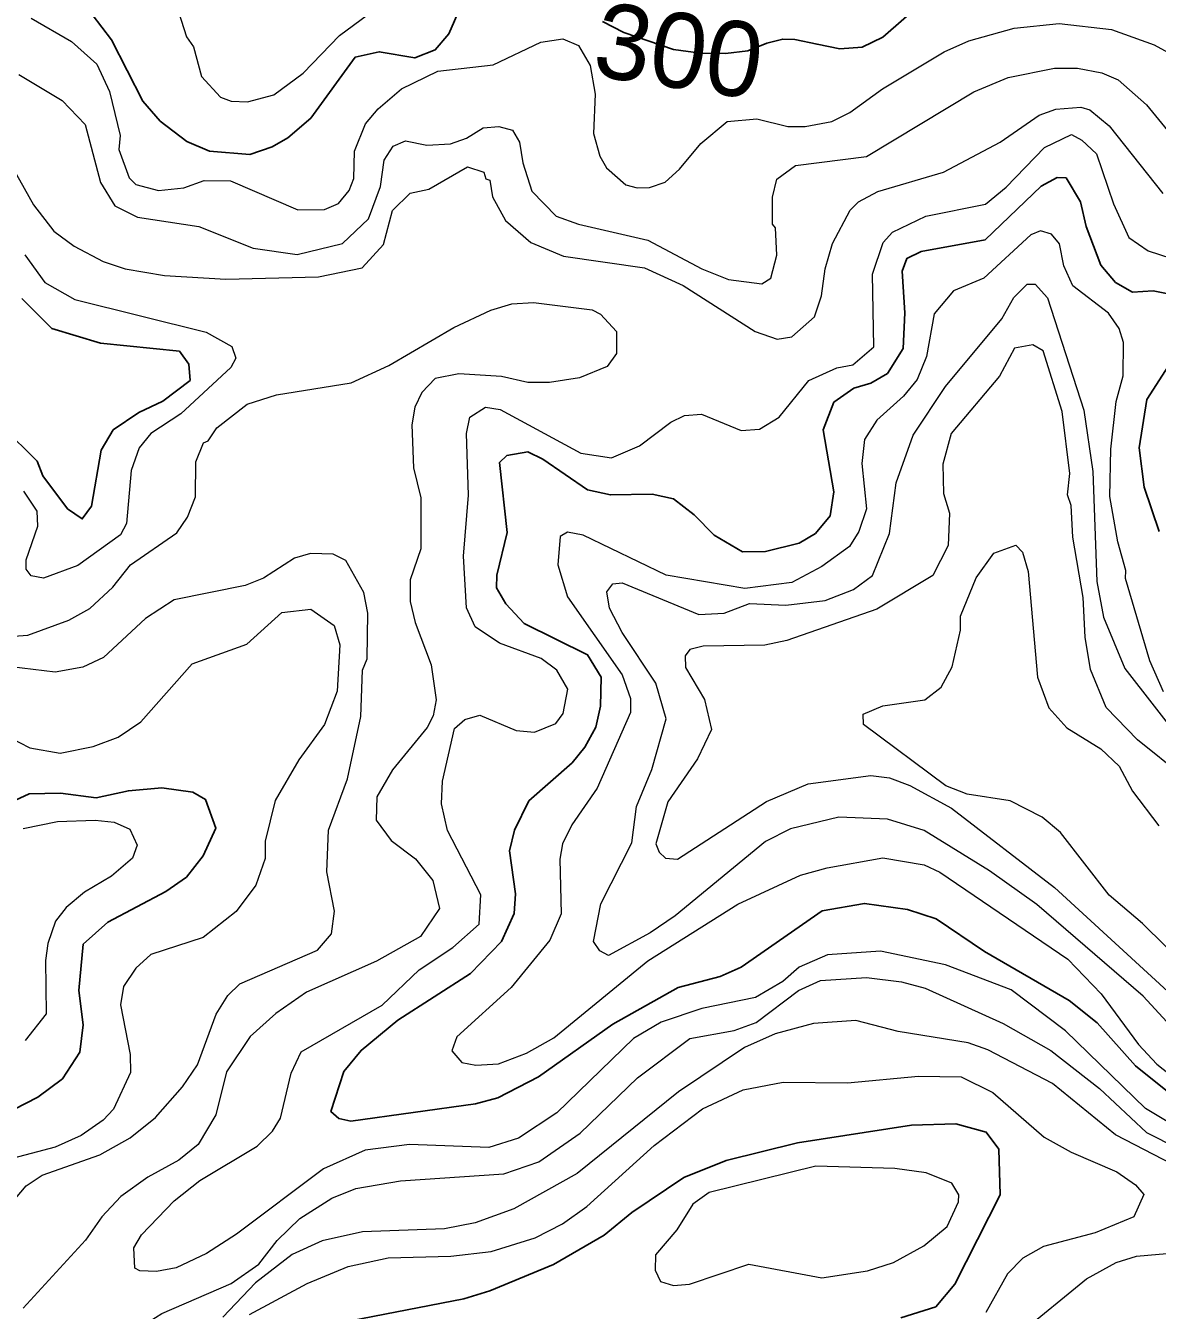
# Model space of a CAD drawing. Extents: x 673.6 to 698.9, y 7012 to 7040.1.
# Drawn here: x 687.168 to 688.374, y 7015.259 to 7016.629 of the extents above; entities that cross this region are included whole.
import ezdxf
from ezdxf.enums import TextEntityAlignment as Align

# ---------------------------------------------------------------- set-up
doc = ezdxf.new("R2010")
doc.units = 0
doc.header["$LTSCALE"] = 0.032
doc.layers.add('1', color=7, linetype='Continuous', lineweight=25)
doc.layers.add('2', color=7, linetype='Continuous', lineweight=13)
doc.layers.add('61', color=7, linetype='Continuous')

msp = doc.modelspace()

# ---------------------------------------------------------------- linework, layer by layer
at = {"layer": '1'}
for points in [[(687.2385, 7016.6409), (687.2594, 7016.6137), (687.2927, 7016.5483), (687.3111, 7016.5273), (687.3397, 7016.5055), (687.3639, 7016.495), (687.4067, 7016.4917), (687.4305, 7016.4996), (687.4472, 7016.5092), (687.4716, 7016.5304), (687.5189, 7016.5953), (687.5448, 7016.6011), (687.5825, 7016.5945), (687.6045, 7016.6033), (687.6189, 7016.6202), (687.6311, 7016.6479)], [(687.7826, 7016.6335), (687.8056, 7016.6218), (687.8586, 7016.6034), (687.8873, 7016.5996), (687.9139, 7016.5993), (687.9376, 7016.6022), (687.9581, 7016.6102), (687.9749, 7016.6147), (687.988, 7016.6141), (688.0115, 7016.6092), (688.0357, 7016.6043), (688.0595, 7016.6061), (688.0816, 7016.6168), (688.1237, 7016.6532)], [(688.1052, 7016.3226), (688.1024, 7016.3672), (688.1073, 7016.3808), (688.1224, 7016.3882), (688.1909, 7016.4007), (688.2504, 7016.4577)], [(688.2504, 7016.4577), (688.2674, 7016.467), (688.2771, 7016.4667), (688.2923, 7016.4411), (688.2983, 7016.4148), (688.314, 7016.3734), (688.3299, 7016.3549), (688.348, 7016.3446), (688.3699, 7016.3461), (688.4022, 7016.3397)], [(687.1637, 7016.3381), (687.1956, 7016.306), (687.2476, 7016.2903), (687.3317, 7016.282), (687.3416, 7016.2681), (687.343, 7016.2507), (687.3139, 7016.2284), (687.2883, 7016.2163), (687.261, 7016.1979), (687.2482, 7016.1761), (687.2379, 7016.1164), (687.2281, 7016.1029), (687.2124, 7016.1136), (687.1859, 7016.1489), (687.1799, 7016.1644), (687.1433, 7016.2008)], [(688.3851, 7015.4922), (688.351, 7015.5196), (688.3102, 7015.5656), (688.2802, 7015.5895), (688.1902, 7015.6417), (688.1384, 7015.6763), (688.108, 7015.6864), (688.062, 7015.6929), (688.0168, 7015.6848), (687.9305, 7015.625), (687.9083, 7015.615), (687.8636, 7015.6033), (687.7937, 7015.5642), (687.7145, 7015.5078), (687.671, 7015.4857), (687.6474, 7015.4791), (687.5145, 7015.4605), (687.5015, 7015.4636), (687.4932, 7015.4709), (687.507, 7015.5138), (687.5253, 7015.5362), (687.5644, 7015.5685), (687.6419, 7015.618), (687.6752, 7015.6524), (687.6886, 7015.6823), (687.69, 7015.7031), (687.6837, 7015.7488), (687.6889, 7015.7711), (687.7042, 7015.8022), (687.7504, 7015.8429), (687.7639, 7015.8594), (687.7757, 7015.8807), (687.7805, 7015.9033), (687.7814, 7015.9342), (687.7668, 7015.958), (687.6993, 7015.9913), (687.6798, 7016.0123), (687.6699, 7016.0295), (687.67, 7016.043), (687.6812, 7016.0883), (687.6731, 7016.163), (687.6807, 7016.1704), (687.703, 7016.1744), (687.7193, 7016.1668), (687.7667, 7016.134), (687.7912, 7016.1285), (687.8356, 7016.1292), (687.8586, 7016.1242), (687.8805, 7016.1073), (687.9017, 7016.0855), (687.9322, 7016.0678), (687.9567, 7016.0682), (687.9926, 7016.0772), (688.0098, 7016.0874), (688.0256, 7016.1064), (688.0294, 7016.1319), (688.0182, 7016.1979), (688.0293, 7016.2273), (688.0506, 7016.2425), (688.069, 7016.2477), (688.0868, 7016.2582), (688.1032, 7016.2848), (688.1052, 7016.3226)], [(688.4088, 7016.3011), (688.3633, 7016.2303), (688.355, 7016.1788), (688.3604, 7016.1367), (688.3762, 7016.0894)], [(687.1057, 7015.7797), (687.1716, 7015.8096), (687.2047, 7015.8105), (687.2429, 7015.8056), (687.2772, 7015.813), (687.3128, 7015.8162), (687.346, 7015.8116), (687.3595, 7015.8038), (687.3704, 7015.7731), (687.3571, 7015.7436), (687.3391, 7015.7209), (687.3171, 7015.7056), (687.2552, 7015.673), (687.2292, 7015.6496), (687.2243, 7015.6001), (687.2291, 7015.5635), (687.2253, 7015.5341), (687.207, 7015.5059), (687.1806, 7015.4863), (687.1042, 7015.4472)], [(687.5139, 7015.2476), (687.6348, 7015.2713), (687.6627, 7015.2798), (687.7304, 7015.3079), (687.7846, 7015.339), (687.8141, 7015.3631), (687.8693, 7015.4007), (687.9145, 7015.4188), (687.9905, 7015.4374), (688.1121, 7015.4563), (688.1594, 7015.4579), (688.1919, 7015.449), (688.2053, 7015.4308), (688.2068, 7015.382), (688.1583, 7015.2868), (688.138, 7015.2628), (688.101, 7015.2508)]]:
    msp.add_lwpolyline(points, dxfattribs=at)
at = {"layer": '2'}
for points in [[(687.0418, 7016.6363), (687.0645, 7016.5815), (687.0906, 7016.5473), (687.1226, 7016.5234), (687.1479, 7016.488), (687.1762, 7016.4378)], [(687.1737, 7016.6368), (687.2166, 7016.6121), (687.2435, 7016.588), (687.2572, 7016.5587), (687.2685, 7016.5118), (687.2672, 7016.4969), (687.2781, 7016.4668), (687.2852, 7016.4597), (687.3094, 7016.4531), (687.3365, 7016.4561), (687.3581, 7016.4638), (687.386, 7016.4636), (687.4579, 7016.4325), (687.4863, 7016.4328), (687.5013, 7016.4393), (687.5128, 7016.4532), (687.5177, 7016.4661), (687.5185, 7016.495), (687.53, 7016.5243), (687.5434, 7016.5404), (687.5686, 7016.5617), (687.6072, 7016.5804), (687.6661, 7016.5873), (687.717, 7016.6115), (687.7406, 7016.615), (687.7572, 7016.6078), (687.7695, 7016.5864), (687.7748, 7016.5558), (687.7733, 7016.5141), (687.7799, 7016.4897), (687.7869, 7016.4773), (687.8076, 7016.4593)], [(687.3307, 7016.6439), (687.3391, 7016.6172), (687.3467, 7016.6064), (687.3553, 7016.5749), (687.3753, 7016.5528), (687.3869, 7016.5484), (687.4042, 7016.5476), (687.4323, 7016.5552), (687.4636, 7016.5782), (687.5022, 7016.6185), (687.5322, 7016.6407)], [(687.8877, 7016.5034), (687.9157, 7016.5269), (687.9473, 7016.5295), (687.9803, 7016.5213), (687.999, 7016.5213), (688.0272, 7016.5268), (688.0463, 7016.5362), (688.0814, 7016.5615), (688.1471, 7016.6009), (688.1732, 7016.6127), (688.2218, 7016.6264), (688.2695, 7016.6313), (688.3254, 7016.6248), (688.3711, 7016.6085), (688.4555, 7016.5622), (688.4839, 7016.5575), (688.5124, 7016.5655), (688.5637, 7016.5952), (688.5831, 7016.6033), (688.6472, 7016.6182), (688.7021, 7016.6375)], [(688.2892, 7016.5837), (688.315, 7016.5787), (688.3326, 7016.5713), (688.3629, 7016.5445), (688.3917, 7016.5092), (688.4241, 7016.4864), (688.4442, 7016.4798), (688.4802, 7016.4792), (688.4969, 7016.4827), (688.5131, 7016.4926), (688.5245, 7016.4952), (688.6344, 7016.559), (688.7191, 7016.5916), (688.7324, 7016.5909), (688.758, 7016.5998), (689.0062, 7016.6282), (689.0534, 7016.6389)], [(687.9884, 7016.4799), (688.0644, 7016.4894), (688.1787, 7016.5584), (688.2153, 7016.5738), (688.2646, 7016.5837), (688.2892, 7016.5837)], [(687.1606, 7016.5768), (687.2065, 7016.549), (687.2311, 7016.5234), (687.2474, 7016.4618), (687.2628, 7016.4369), (687.2869, 7016.4247), (687.3523, 7016.4147), (687.4102, 7016.3918), (687.4573, 7016.3849), (687.5056, 7016.3966), (687.5334, 7016.423), (687.5461, 7016.4576), (687.5498, 7016.4854), (687.5596, 7016.5006), (687.5726, 7016.5063), (687.5954, 7016.5016), (687.6207, 7016.503), (687.6378, 7016.5089), (687.6554, 7016.5199), (687.6722, 7016.5213), (687.6867, 7016.5177), (687.6943, 7016.5047), (687.6977, 7016.4827), (687.7073, 7016.4526), (687.7333, 7016.4258), (687.7571, 7016.4173), (687.831, 7016.4003), (687.8888, 7016.3697), (687.917, 7016.3583), (687.9528, 7016.3537), (687.9623, 7016.3597), (687.9686, 7016.3844), (687.9671, 7016.4133), (687.9639, 7016.4172), (687.9639, 7016.446), (687.9687, 7016.4651), (687.9884, 7016.4799)], [(687.1762, 7016.4378), (687.1977, 7016.4098), (687.2196, 7016.3937), (687.2505, 7016.3774), (687.2738, 7016.3696), (687.3158, 7016.3625), (687.3813, 7016.3586), (687.4798, 7016.3611), (687.5264, 7016.3708), (687.5493, 7016.3955), (687.559, 7016.4318), (687.5778, 7016.4505), (687.5975, 7016.4547), (687.6387, 7016.4783), (687.6562, 7016.4728), (687.6583, 7016.4657), (687.6628, 7016.4643), (687.6656, 7016.4466), (687.6795, 7016.4211), (687.7064, 7016.3978), (687.741, 7016.3831), (687.8277, 7016.3707), (687.8689, 7016.3519), (687.9454, 7016.3028), (687.9691, 7016.2945), (687.9847, 7016.297), (688.0088, 7016.3183), (688.0164, 7016.3408), (688.02, 7016.3696), (688.0281, 7016.3968), (688.0467, 7016.4322), (688.0556, 7016.4412), (688.0762, 7016.4522), (688.1464, 7016.4727), (688.2068, 7016.5047), (688.2482, 7016.5335), (688.2662, 7016.5401), (688.2926, 7016.5419), (688.3022, 7016.5392), (688.3229, 7016.5221), (688.3802, 7016.4501)], [(688.3937, 7015.4549), (688.3618, 7015.4742), (688.2763, 7015.5571), (688.2185, 7015.6009), (688.1484, 7015.6273), (688.0793, 7015.642), (688.0227, 7015.6381), (687.9925, 7015.625), (687.9751, 7015.6096), (687.9458, 7015.5925), (687.8887, 7015.5808), (687.8452, 7015.5663), (687.8157, 7015.5489), (687.734, 7015.4697), (687.6932, 7015.4427), (687.6614, 7015.4325), (687.5768, 7015.4358), (687.5296, 7015.4298), (687.4854, 7015.4099), (687.3925, 7015.3401), (687.3604, 7015.3197), (687.3281, 7015.3044), (687.3072, 7015.3002), (687.2894, 7015.3009), (687.2842, 7015.304), (687.2831, 7015.3255), (687.2911, 7015.3395), (687.3261, 7015.3757), (687.3535, 7015.3973), (687.4146, 7015.4339), (687.4309, 7015.4499), (687.4395, 7015.464), (687.4509, 7015.5118), (687.4614, 7015.5347), (687.5477, 7015.5842), (687.5872, 7015.622), (687.623, 7015.646), (687.6514, 7015.6709), (687.6531, 7015.7021), (687.6175, 7015.7706), (687.611, 7015.7992), (687.6122, 7015.8231), (687.6249, 7015.8794), (687.6359, 7015.8892), (687.6518, 7015.8935), (687.6907, 7015.8772), (687.7102, 7015.8755), (687.7329, 7015.8848), (687.7407, 7015.8953), (687.7459, 7015.9212), (687.7339, 7015.9417), (687.7173, 7015.9542), (687.6729, 7015.9706), (687.6469, 7015.9879), (687.6377, 7016.0082), (687.6344, 7016.0631), (687.6399, 7016.1281), (687.6376, 7016.1942), (687.6412, 7016.2115), (687.6581, 7016.222), (687.6738, 7016.2196), (687.7597, 7016.173), (687.7925, 7016.168), (687.8223, 7016.1809), (687.8555, 7016.2061), (687.8701, 7016.2133), (687.8882, 7016.2146), (687.9305, 7016.1973), (687.95, 7016.1986), (687.9712, 7016.2115), (688.0029, 7016.2505), (688.0326, 7016.2642), (688.0498, 7016.2673), (688.0721, 7016.2865), (688.0707, 7016.3639), (688.082, 7016.3977), (688.0921, 7016.4086), (688.1275, 7016.4257), (688.191, 7016.4386), (688.2131, 7016.4566), (688.2542, 7016.4992), (688.2827, 7016.5129), (688.2938, 7016.5068), (688.3093, 7016.4922), (688.3277, 7016.439), (688.3441, 7016.4032), (688.3644, 7016.389), (688.402, 7016.3769)], [(687.8076, 7016.4593), (687.8196, 7016.4559), (687.833, 7016.4564), (687.8496, 7016.4622), (687.865, 7016.4758), (687.8877, 7016.5034)], [(688.3809, 7015.9184), (688.3663, 7015.9517), (688.3404, 7016.0394), (688.3409, 7016.0481), (688.3322, 7016.0785), (688.3238, 7016.1269), (688.3247, 7016.1772), (688.3304, 7016.2283), (688.3378, 7016.2557), (688.3381, 7016.2911), (688.3336, 7016.3059), (688.3221, 7016.3223), (688.2843, 7016.3516), (688.2746, 7016.373), (688.2701, 7016.3964), (688.2615, 7016.4067), (688.2497, 7016.4102), (688.2393, 7016.4059), (688.1893, 7016.3596), (688.157, 7016.3462), (688.1363, 7016.3218), (688.1281, 7016.2761), (688.1183, 7016.2518), (688.1038, 7016.2339), (688.0754, 7016.2082), (688.0622, 7016.1877), (688.0591, 7016.1619), (688.0641, 7016.1138), (688.056, 7016.0894), (688.0461, 7016.0735), (688.0167, 7016.0522), (687.9846, 7016.0352), (687.9346, 7016.0286), (687.8508, 7016.043), (687.762, 7016.0856), (687.7453, 7016.0889), (687.7376, 7016.0843), (687.7353, 7016.054), (687.7454, 7016.0197), (687.8037, 7015.9366), (687.8126, 7015.9115), (687.8126, 7015.8966), (687.7771, 7015.8159), (687.7502, 7015.7767), (687.7401, 7015.7563), (687.7371, 7015.74), (687.7386, 7015.6818), (687.7265, 7015.6538), (687.6852, 7015.6033), (687.6276, 7015.5507), (687.6221, 7015.5357), (687.6328, 7015.5233), (687.6476, 7015.5204), (687.6719, 7015.5218), (687.7016, 7015.5331), (687.731, 7015.5496), (687.831, 7015.6315), (687.9269, 7015.6921), (687.9939, 7015.7229), (688.0224, 7015.731), (688.0815, 7015.7414), (688.1259, 7015.7342), (688.1424, 7015.7262), (688.2788, 7015.6335), (688.3145, 7015.5963), (688.3544, 7015.5424), (688.3737, 7015.5213), (688.3957, 7015.5039)], [(687.1669, 7016.3845), (687.1883, 7016.355), (687.22, 7016.3371), (687.3601, 7016.3022), (687.3876, 7016.2869), (687.3919, 7016.2744), (687.3865, 7016.2643), (687.3332, 7016.2151), (687.3013, 7016.194), (687.2888, 7016.1788), (687.2801, 7016.1544), (687.2754, 7016.0979), (687.2688, 7016.0861), (687.2233, 7016.0532), (687.1867, 7016.0399), (687.1735, 7016.0422), (687.1684, 7016.0492), (687.1684, 7016.0594), (687.1806, 7016.0953), (687.1799, 7016.1113), (687.1657, 7016.1327)], [(687.9566, 7015.759), (687.8601, 7015.6795), (687.8337, 7015.6615), (687.7893, 7015.6375), (687.7798, 7015.6423), (687.7733, 7015.6522), (687.7811, 7015.6926), (687.8142, 7015.7575), (687.8191, 7015.7962), (687.8355, 7015.8356), (687.8505, 7015.8899), (687.8397, 7015.9279), (687.8038, 7015.9818), (687.7902, 7016.0076), (687.7872, 7016.0251), (687.7936, 7016.0337), (687.8038, 7016.0347), (687.8853, 7016.001), (687.9125, 7016.0023), (687.9396, 7016.0126), (687.9784, 7016.011), (688.02, 7016.0158), (688.0504, 7016.0275), (688.0707, 7016.0425), (688.0887, 7016.0874), (688.0957, 7016.1413), (688.1141, 7016.1922), (688.1485, 7016.2442), (688.2085, 7016.3164), (688.2213, 7016.3391), (688.2354, 7016.3532), (688.2442, 7016.3534), (688.2572, 7016.3386), (688.2958, 7016.2188), (688.3057, 7016.1535), (688.3097, 7016.0362), (688.317, 7015.9983), (688.3398, 7015.9434), (688.3996, 7015.8663)], [(687.1249, 7015.9757), (687.17, 7015.979), (687.2137, 7015.9951), (687.2363, 7016.0073), (687.2607, 7016.0301), (687.2796, 7016.0539), (687.329, 7016.088), (687.3401, 7016.1047), (687.3489, 7016.1265), (687.3492, 7016.1638), (687.3575, 7016.1842), (687.3622, 7016.1863), (687.3715, 7016.2001), (687.404, 7016.2252), (687.435, 7016.2354), (687.5149, 7016.2481), (687.5548, 7016.2667), (687.6243, 7016.3071), (687.6637, 7016.3255), (687.6862, 7016.3322), (687.7091, 7016.3339), (687.7716, 7016.3258), (687.7807, 7016.3214), (687.7976, 7016.3028), (687.7978, 7016.2792), (687.7876, 7016.2656), (687.7581, 7016.2533), (687.7263, 7016.2485), (687.7033, 7016.2485), (687.675, 7016.255), (687.6295, 7016.2575), (687.6045, 7016.2527), (687.59, 7016.2377), (687.5825, 7016.2222), (687.5793, 7016.2032), (687.5811, 7016.1575), (687.5891, 7016.1256), (687.5891, 7016.071), (687.5777, 7016.0381), (687.5777, 7016.0147), (687.5829, 7015.9925), (687.5999, 7015.9474), (687.6055, 7015.9099), (687.6021, 7015.893), (687.5957, 7015.8805), (687.559, 7015.8353), (687.5423, 7015.8065), (687.5415, 7015.7816), (687.5573, 7015.7601), (687.5833, 7015.7406), (687.602, 7015.7175), (687.6088, 7015.6875), (687.5887, 7015.6575), (687.5419, 7015.6312), (687.467, 7015.5983), (687.4344, 7015.5754), (687.407, 7015.551), (687.3817, 7015.5132), (687.3704, 7015.4675), (687.3517, 7015.4359), (687.3311, 7015.419), (687.298, 7015.4009), (687.2692, 7015.3803), (687.2491, 7015.3587), (687.2314, 7015.3336), (687.1649, 7015.2612)], [(688.402, 7015.8281), (688.3531, 7015.8674), (688.3197, 7015.9018), (688.3029, 7015.9425), (688.2973, 7015.9769), (688.2951, 7016.0193), (688.2844, 7016.0834), (688.2826, 7016.1172), (688.2786, 7016.1288), (688.281, 7016.1515), (688.2728, 7016.2176), (688.2527, 7016.2822), (688.2415, 7016.2886), (688.2222, 7016.2849), (688.2061, 7016.2552), (688.1546, 7016.1942), (688.1455, 7016.1613), (688.1463, 7016.1301), (688.1527, 7016.1091), (688.1512, 7016.0746), (688.1349, 7016.0426), (688.0753, 7016.0067), (687.9793, 7015.9734), (687.956, 7015.9683), (687.89, 7015.9674), (687.8758, 7015.9638), (687.871, 7015.957), (687.8713, 7015.9446), (687.8914, 7015.9102), (687.8988, 7015.8783), (687.8839, 7015.8471), (687.8525, 7015.8011), (687.8397, 7015.7566), (687.843, 7015.7476), (687.8499, 7015.7411), (687.8627, 7015.7399), (687.9576, 7015.8016), (688.002, 7015.8204), (688.069, 7015.8293), (688.0887, 7015.8269), (688.1105, 7015.8185), (688.1548, 7015.7946), (688.2648, 7015.71), (688.3941, 7015.5913)], [(688.4555, 7015.576), (688.3585, 7015.6713), (688.323, 7015.7018), (688.2711, 7015.7685), (688.2517, 7015.7847), (688.2174, 7015.8023), (688.1716, 7015.8095), (688.1489, 7015.8183), (688.0609, 7015.8836), (688.0608, 7015.8947), (688.0817, 7015.9036), (688.1264, 7015.9099), (688.1439, 7015.9234), (688.1555, 7015.9451), (688.1643, 7015.9842), (688.1644, 7015.9991), (688.181, 7016.0401), (688.2001, 7016.0664), (688.2233, 7016.075), (688.2305, 7016.0674), (688.2366, 7016.0467), (688.2466, 7015.9342), (688.2588, 7015.9016), (688.278, 7015.8801), (688.3142, 7015.8579), (688.3336, 7015.8392), (688.3478, 7015.8126), (688.3759, 7015.7756)], [(687.1531, 7015.3736), (687.1682, 7015.3918), (687.1854, 7015.403), (687.2468, 7015.4248), (687.2791, 7015.4428), (687.3062, 7015.4645), (687.3348, 7015.4972), (687.351, 7015.5208), (687.3707, 7015.5749), (687.3831, 7015.5946), (687.3962, 7015.6071), (687.4789, 7015.6429), (687.4937, 7015.6606), (687.497, 7015.6847), (687.4889, 7015.7267), (687.4907, 7015.771), (687.5109, 7015.8257), (687.5251, 7015.8922), (687.5267, 7015.9416), (687.5317, 7015.9538), (687.5324, 7016.0026), (687.5283, 7016.0246), (687.5091, 7016.0587), (687.4955, 7016.0652), (687.4713, 7016.066), (687.4543, 7016.0611), (687.4214, 7016.0399), (687.4019, 7016.0318), (687.3259, 7016.0165), (687.2955, 7015.9966), (687.2508, 7015.9553), (687.2285, 7015.945), (687.1991, 7015.9395), (687.1523, 7015.9452)], [(687.1501, 7015.8701), (687.1722, 7015.8588), (687.2046, 7015.8532), (687.2396, 7015.8603), (687.2664, 7015.8701), (687.2905, 7015.8865), (687.3451, 7015.9485), (687.4037, 7015.9692), (687.4409, 7016.0033), (687.4716, 7016.0068), (687.4965, 7015.9891), (687.5028, 7015.9687), (687.4997, 7015.9192), (687.4864, 7015.8837), (687.4589, 7015.846), (687.4337, 7015.8026), (687.4232, 7015.7591), (687.4231, 7015.7407), (687.413, 7015.7123), (687.3921, 7015.6841), (687.357, 7015.6567), (687.3012, 7015.6385), (687.2851, 7015.6239), (687.272, 7015.6042), (687.2687, 7015.5848), (687.2793, 7015.5319), (687.2794, 7015.5125), (687.2613, 7015.4734), (687.2503, 7015.4617), (687.2269, 7015.4453), (687.199, 7015.433), (687.122, 7015.4126)], [(688.1954, 7015.7278), (688.1258, 7015.7705), (688.0868, 7015.7826), (688.0349, 7015.7849), (687.9833, 7015.7725), (687.9566, 7015.759)], [(687.1652, 7015.7727), (687.2016, 7015.7801), (687.2418, 7015.7818), (687.262, 7015.7796), (687.2789, 7015.772), (687.2867, 7015.7551), (687.2816, 7015.7413), (687.2594, 7015.7221), (687.2303, 7015.7048), (687.2108, 7015.6886), (687.1996, 7015.6739), (687.1915, 7015.6502), (687.189, 7015.6321), (687.1897, 7015.575), (687.1671, 7015.5468)], [(688.435, 7015.5119), (688.3593, 7015.5941), (688.2459, 7015.6919), (688.1954, 7015.7278)], [(687.8758, 7015.549), (687.9231, 7015.5574), (687.9467, 7015.566), (687.9918, 7015.6001), (688.0153, 7015.6107), (688.0641, 7015.614)], [(688.0641, 7015.614), (688.1016, 7015.6092), (688.1268, 7015.6024), (688.21, 7015.5649), (688.2607, 7015.536), (688.3125, 7015.4955), (688.3627, 7015.4486), (688.4289, 7015.4152)], [(688.3909, 7015.4145), (688.3297, 7015.4461), (688.2626, 7015.5008), (688.1935, 7015.5369), (688.1725, 7015.5442), (688.0981, 7015.5563), (688.053, 7015.568), (688.0079, 7015.5647), (687.9668, 7015.5539), (687.9343, 7015.5392), (687.8639, 7015.4918), (687.7557, 7015.405), (687.6883, 7015.3671), (687.6469, 7015.3524), (687.6142, 7015.3459), (687.5267, 7015.3428), (687.4839, 7015.333), (687.4517, 7015.3186), (687.4127, 7015.2881), (687.3779, 7015.2518)], [(687.1569, 7015.2389), (687.1701, 7015.2227), (687.2066, 7015.2197), (687.2617, 7015.2294), (687.2927, 7015.2428), (687.3129, 7015.2557), (687.387, 7015.2875), (687.4162, 7015.3081), (687.436, 7015.3335), (687.4602, 7015.3568), (687.4942, 7015.3784), (687.5198, 7015.3888), (687.5674, 7015.3971), (687.6775, 7015.4045), (687.7149, 7015.4173), (687.759, 7015.4477), (687.8199, 7015.507), (687.8758, 7015.549)], [(687.4064, 7015.2545), (687.4678, 7015.2876), (687.5116, 7015.3058), (687.5543, 7015.3149), (687.6211, 7015.3166), (687.6639, 7015.3217), (687.7108, 7015.3362), (687.74, 7015.351), (687.7659, 7015.3698), (687.8379, 7015.4346), (687.8894, 7015.4737), (687.9326, 7015.494), (687.9753, 7015.5023), (688.0439, 7015.5015), (688.1197, 7015.5088), (688.1651, 7015.5078), (688.1991, 7015.4914), (688.2538, 7015.4436), (688.2826, 7015.4275), (688.331, 7015.4065), (688.3511, 7015.3926), (688.3598, 7015.3825), (688.3493, 7015.3588)], [(688.3493, 7015.3588), (688.308, 7015.3415), (688.2528, 7015.3271), (688.2311, 7015.3145), (688.2146, 7015.2979), (688.1913, 7015.2567)], [(687.5897, 7015.0015), (687.6282, 7015.0369), (687.6595, 7015.051), (687.6821, 7015.0568), (687.7252, 7015.061), (687.7818, 7015.0611), (687.8366, 7015.0698), (687.8674, 7015.0879), (687.9115, 7015.1269), (687.9717, 7015.1635), (688.0069, 7015.1745), (688.1179, 7015.1994), (688.171, 7015.2163), (688.1946, 7015.2207), (688.2265, 7015.2335), (688.2989, 7015.2925), (688.3304, 7015.31), (688.3521, 7015.3166), (688.3965, 7015.3207)]]:
    msp.add_lwpolyline(points, dxfattribs=at)
msp.add_lwpolyline([(687.9389, 7015.3082), (688.0167, 7015.2936), (688.0653, 7015.301), (688.093, 7015.3098), (688.1254, 7015.3276), (688.1501, 7015.3484), (688.1623, 7015.3747), (688.1626, 7015.3822), (688.1552, 7015.3945), (688.1279, 7015.4054), (688.0944, 7015.4102), (688.0102, 7015.4127), (687.8964, 7015.3847), (687.879, 7015.372), (687.8621, 7015.3448), (687.8391, 7015.318), (687.839, 7015.3018), (687.8445, 7015.2897), (687.8586, 7015.2854), (687.8756, 7015.2868)], close=True, dxfattribs=at)

# ---------------------------------------------------------------- texts
at = {"layer": '61'}
msp.add_text('300', height=0.08, rotation=351.703, dxfattribs=at).set_placement((687.8586, 7016.563), align=Align.CENTER)

doc.saveas('drawing.dxf')
